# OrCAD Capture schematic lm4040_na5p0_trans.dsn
size A; title: LM4040-N/-Q1 Precision Micropower Shunt Voltage Reference; rev: 1.1; note: SNOS633N - DECEMBER 1991 - REVISED AUGUST 2025
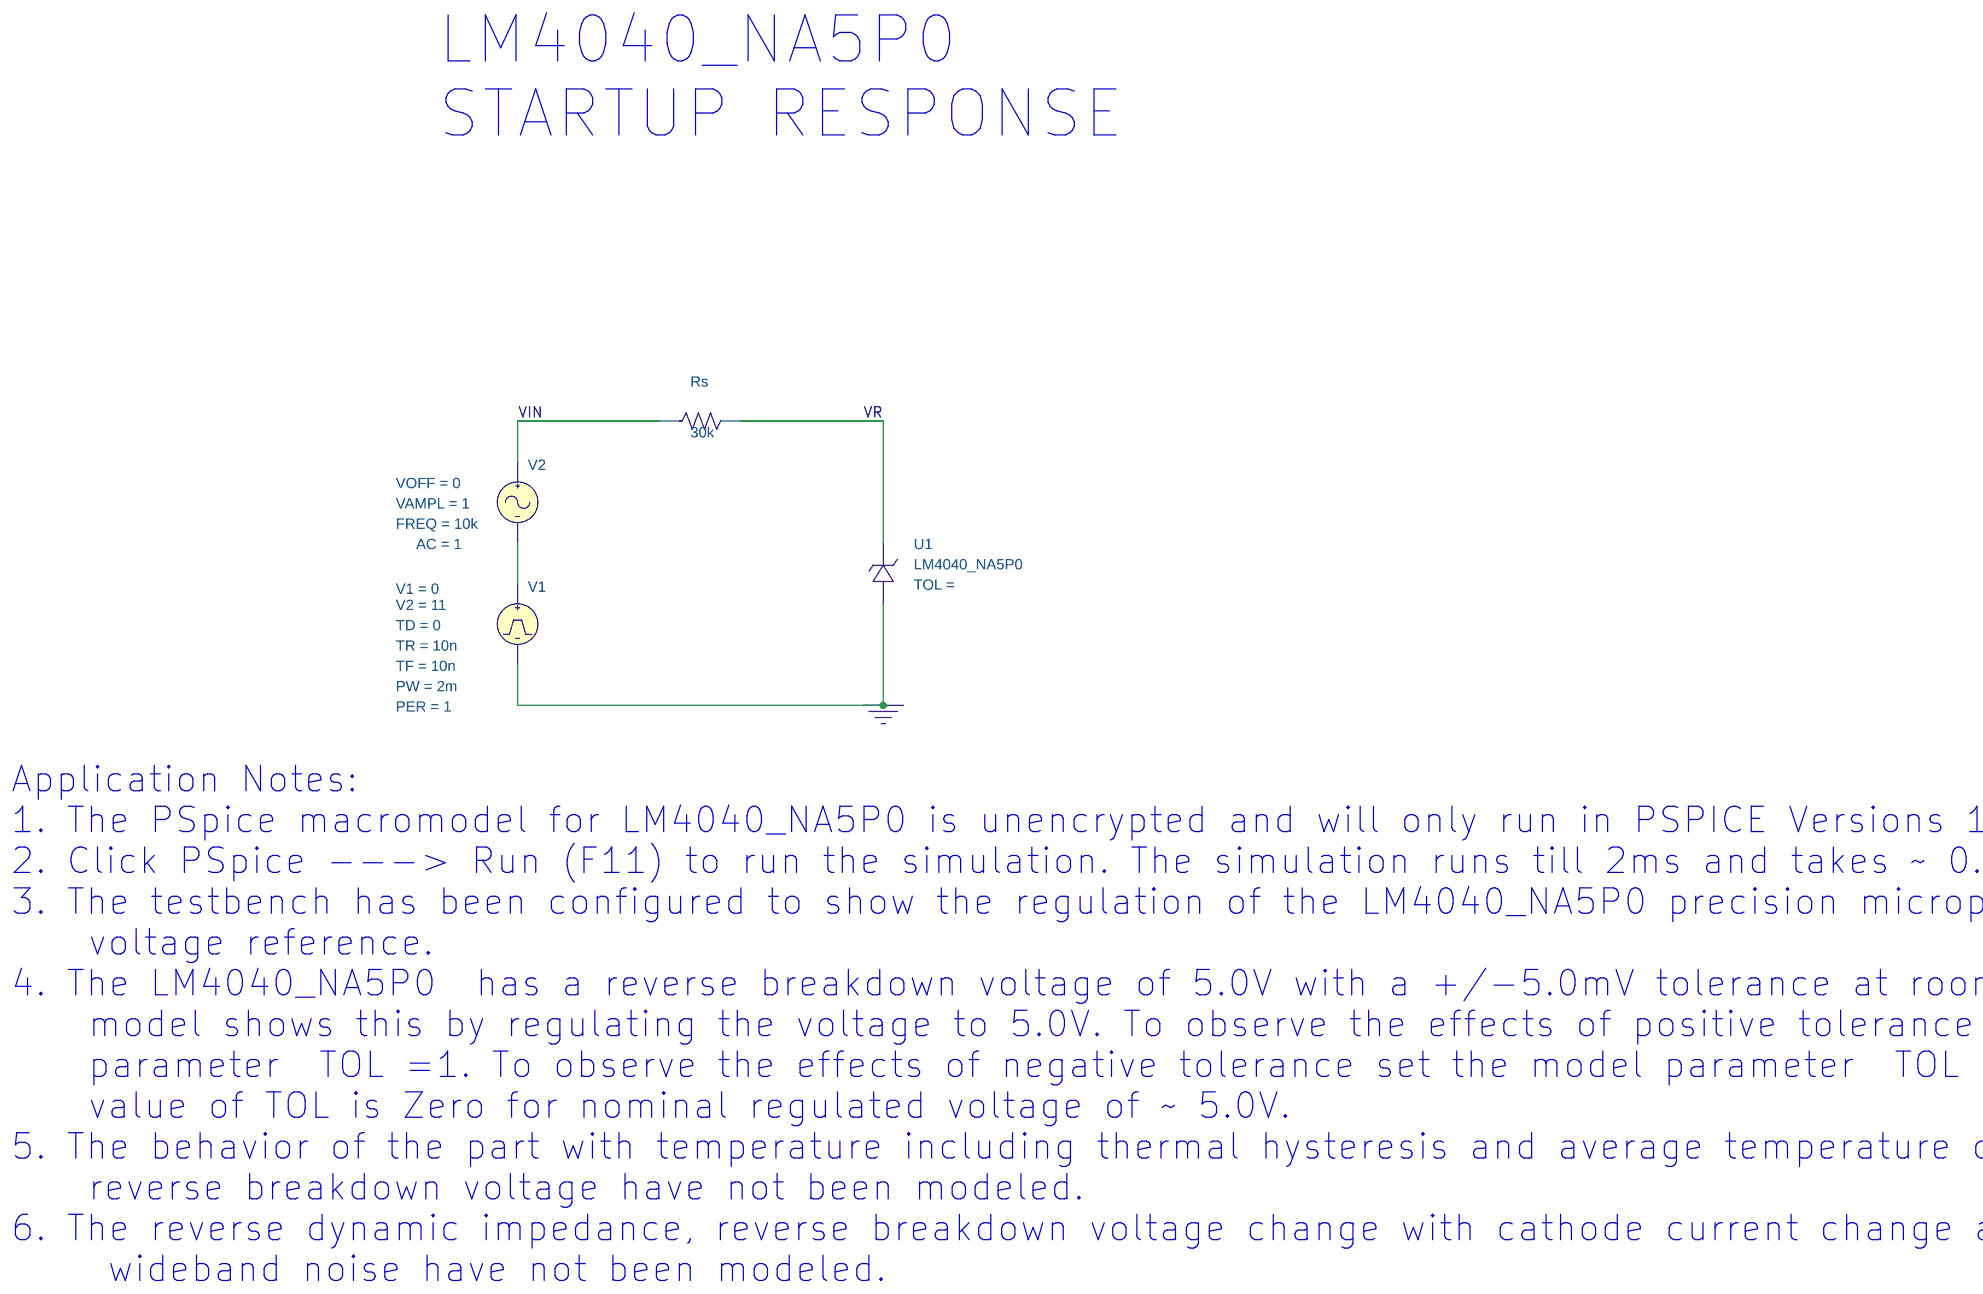
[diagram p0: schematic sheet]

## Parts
Rs  30k  [AXRC05]
U1  LM4040_NA5P0
V1  VPULSE
V2  VSIN

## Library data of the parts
Rs = R
U1 = LM4040_NA5P0
V1 = VPULSE: PER: 1; PW: 2m; TD: 0; TF: 10n; TR: 10n; V1: 0; V2: 11
V2 = VSIN: AC: 1; FREQ: 10k; VAMPL: 1; VOFF: 0

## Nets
VIN: Rs.1 V2.1(+)
0: U1.2(V-) V1.2(-)
VR: Rs.2 U1.1(V+)
N16775380: V1.1(+) V2.2(-)

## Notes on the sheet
- LM4040_NA5P0
  STARTUP RESPONSE
- Application Notes:
  1. The PSpice macromodel for LM4040_NA5P0 is unencrypted and will only run in PSPICE Versions 15.7 and up.
  2. Click PSpice ---> Run (F11) to run the simulation. The simulation runs till 2ms and takes ~ 0.5min to run on a 1.8GHz machine.
  3. The testbench has been configured to show the regulation of the LM4040_NA5P0 precision micropower shunt
      voltage reference.
  4. The LM4040_NA5P0  has a reverse breakdown voltage of 5.0V with a +/-5.0mV tolerance at room temperature. The
      model shows this by regulating the voltage to 5.0V. To observe the effects of positive tolerance set the model
      parameter  TOL =1. To observe the effects of negative tolerance set the model parameter  TOL =-1.The default
      value of TOL is Zero for nominal regulated voltage of ~ 5.0V.
  5. The behavior of the part with temperature including thermal hysteresis and average temperature coefficient of
      reverse breakdown voltage have not been modeled.
  6. The reverse dynamic impedance, reverse breakdown voltage change with cathode current change and
       wideband noise have not been modeled.
